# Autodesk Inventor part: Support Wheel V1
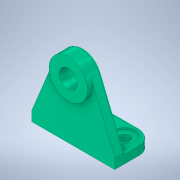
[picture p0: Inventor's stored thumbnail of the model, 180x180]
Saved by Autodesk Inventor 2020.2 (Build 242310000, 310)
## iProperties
Created: 2018-06
Part Number: Support Wheel V1
Material: Iron, Cast
Document SubType Name: Modeling
Designer: Power User
Density: 7.15 g/cm^3
Appearance: Aluminum - Polished(1)
Mass: 471.804 g
Surface Area: 175.665 cm^2
Volume: 65.9865 cm^3
Author: Power User
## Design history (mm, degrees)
sketch "Sketch1"
  geometry: L1 (0, 0)-(0, 60); L2 (-41, 0)-(-41, 10); L3 (-41, 10)-(-17.584, 67.199); L4 (-41, 0)-(0, 0); L5 (41, 10)-(17.584, 67.199); L6 (41, 0)-(41, 10); L7 (41, 0)-(0, 0); L8 (-41, 10)-(41, 10); A1 r 19 centre (0, 60) between (-17.584, 67.199) and (17.584, 67.199)
  constraints: 16 end point, 3 symmetric about line, 3 vertical, 2 point on circle, 1 centre point, 1 coincident, 1 horizontal, 1 tangent
  dimensions: "d0" = 60 distance of L1.start L1.end; "d1" = 38 diameter of A1; "d2" = 10 distance of L2.start L2.end; "d3" = 82 diameter of L2 L1
extrude "Extrusion2" new body sketch "Sketch1" distance "d7" = 10; taper "d8" = 0 deg
extrude "Extrusion3" join sketch "Sketch1" distance "d9" = 38; taper "d10" = 0 deg
extrude "Extrusion4" join sketch "Sketch1" distance "d11" = 5; taper "d12" = 0 deg
sketch "Sketch2"
  geometry: C1 r 19 at (0, 0) reference; 2 further points
  constraints: 1 coincident
hole "Hole1" sketch "Sketch2" at (0, 0) diameter "d13" = 18; stored, may be unused: countersink angle "d17" = 90 deg, drill point angle "d19" = 118 deg; dims "d14" = 6, "d15" = 4, "d16" = 2, "d18" = 8
fillet "Fillet1" dims "d20" = 14
node "Hole4"
sketch "Sketch3"
  geometry: A1 r 14 centre (14, 14) between (14, 28) and (0, 14) reference; A2 r 14 centre (68, 14) between (82, 14) and (68, 28) reference; 3 further points
  constraints: 2 coincident
hole "Hole2" sketch "Sketch3" at (14, 14), (68, 14) diameter "d21" = 10; stored, may be unused: countersink angle "d25" = 90 deg, drill point angle "d27" = 118 deg; dims "d22" = 6, "d23" = 20, "d24" = 2, "d26" = 8
fillet "Fillet2" dims "d28" = 2
body "Solid2"
sketch "Sketch4"
  geometry: 1 further point
hole "Hole3" sketch "Sketch4" diameter "d29" = 9; stored, may be unused: countersink angle "d33" = 90 deg, drill point angle "d35" = 0 deg; dims "d30" = 6, "d31" = 4, "d32" = 2, "d34" = 8
